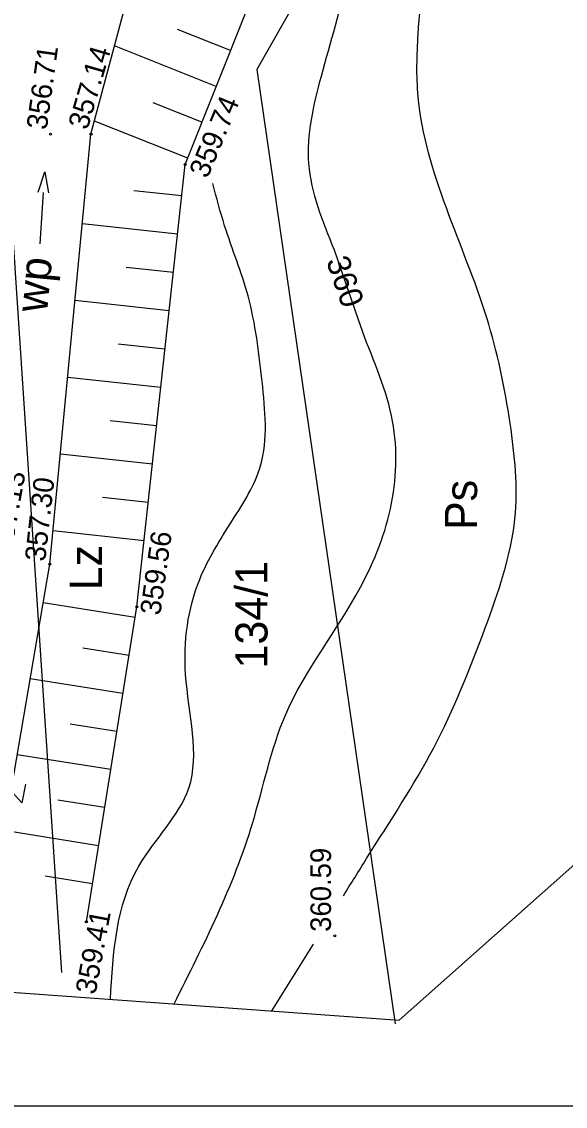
# Model space of a CAD drawing. Extents: x 4635329 to 4651863, y 5356628 to 5367582.
# Drawn here: x 4651202.03 to 4651223.16, y 5356627.73 to 5356669.94 of the extents above; entities that cross this region are included whole.
import ezdxf

# ---------------------------------------------------------------- set-up
doc = ezdxf.new("R2010")
doc.units = 0
for name, color, linetype in [('Level 1', 7, 'Continuous'), ('Level 12', 7, 'Continuous'), ('Level 13', 7, 'Continuous'), ('Level 4', 7, 'Continuous'), ('Level 44', 7, 'Continuous'), ('Level 45', 7, 'Continuous'), ('Level 46', 7, 'Continuous'), ('Level 47', 7, 'Continuous'), ('Level 48', 7, 'Continuous'), ('Level 5', 7, 'Continuous'), ('Level 50', 7, 'Continuous'), ('Level 51', 7, 'Continuous'), ('Level 53', 7, 'Continuous')]:
    doc.layers.add(name, color=color, linetype=linetype)

msp = doc.modelspace()

# ---------------------------------------------------------------- linework, layer by layer
at = {"layer": 'Level 1'}
for p, q in [((4651216.704, 5356631.078), (4651228.549, 5356641.621)), ((4651180.231, 5356633.731), (4651216.704, 5356631.078))]:
    msp.add_line(p, q, dxfattribs=at)
at = {"layer": 'Level 13'}
msp.add_lwpolyline([(4651092.18, 5356627.729), (4651092.18, 5356813.355), (4651331.195, 5356813.355), (4651331.195, 5356627.729)], close=True, dxfattribs=at)
at = {"layer": 'Level 4'}
for p, q in [((4651219.808, 5356683.279), (4651211.17, 5356668.081)), ((4651203.591, 5356632.939), (4651200.98, 5356672.325)), ((4651211.17, 5356668.081), (4651216.545, 5356630.936))]:
    msp.add_line(p, q, dxfattribs=at)
at = {"layer": 'Level 44'}
for centre in [(4651203.155, 5356665.557), (4651204.725, 5356665.557), (4651208.385, 5356664.377), (4651203.125, 5356648.827), (4651206.505, 5356647.167), (4651204.545, 5356634.907), (4651214.205, 5356634.367)]:
    msp.add_circle(centre, 0.04, dxfattribs=at)
at = {"layer": 'Level 46'}
for p, q in [((4651214.997, 5356658.707), (4651214.19, 5356661.051)), ((4651211.76, 5356631.438), (4651213.372, 5356634.04))]:
    msp.add_line(p, q, dxfattribs=at)
for points in [[(4651214.541, 5356635.926), (4651215.44, 5356637.377), (4651218.048, 5356641.682), (4651220.05, 5356646.351), (4651221.202, 5356650.595), (4651221.02, 5356654.294), (4651220.11, 5356658.417), (4651217.442, 5356667.027), (4651217.442, 5356669.452), (4651217.684, 5356673.818), (4651217.017, 5356677.759), (4651216.168, 5356680.79), (4651216.131, 5356681.56)], [(4651214.19, 5356661.051), (4651213.196, 5356664.419), (4651213.681, 5356667.815), (4651214.712, 5356671.756), (4651215.137, 5356675.94), (4651215.076, 5356678.426), (4651215.015, 5356680.305)], [(4651205.478, 5356631.895), (4651206.585, 5356637.074), (4651208.526, 5356640.106), (4651208.404, 5356644.532), (4651208.95, 5356648.23), (4651210.224, 5356650.534), (4651211.316, 5356652.657), (4651211.376, 5356655.931), (4651210.831, 5356659.266), (4651209.921, 5356661.994), (4651209.461, 5356663.637)], [(4651207.952, 5356631.715), (4651211.012, 5356638.772), (4651212.286, 5356642.955), (4651215.197, 5356647.927), (4651216.41, 5356651.201), (4651216.41, 5356654.597), (4651215.197, 5356658.114), (4651214.997, 5356658.707)]]:
    msp.add_spline(points, degree=3, dxfattribs=at)
at = {"layer": 'Level 48'}
for p, q in [((4651210.15, 5356668.811), (4651208.087, 5356669.632)), ((4651209.595, 5356667.417), (4651205.636, 5356668.993)), ((4651209.04, 5356666.023), (4651207.145, 5356666.778)), ((4651208.486, 5356664.63), (4651204.862, 5356666.072)), ((4651208.252, 5356663.156), (4651206.393, 5356663.359)), ((4651208.089, 5356661.665), (4651204.392, 5356662.069)), ((4651207.926, 5356660.174), (4651206.087, 5356660.375)), ((4651207.763, 5356658.683), (4651204.106, 5356659.082)), ((4651207.6, 5356657.192), (4651205.782, 5356657.39)), ((4651207.437, 5356655.701), (4651203.82, 5356656.096)), ((4651207.274, 5356654.209), (4651205.476, 5356654.406)), ((4651207.111, 5356652.718), (4651203.534, 5356653.109)), ((4651206.949, 5356651.227), (4651205.17, 5356651.421)), ((4651206.786, 5356649.736), (4651203.249, 5356650.122)), ((4651206.439, 5356646.757), (4651202.869, 5356647.327)), ((4651206.203, 5356645.275), (4651204.409, 5356645.562)), ((4651205.966, 5356643.794), (4651202.363, 5356644.37)), ((4651205.729, 5356642.313), (4651203.919, 5356642.602)), ((4651205.492, 5356640.832), (4651201.857, 5356641.413)), ((4651205.255, 5356639.351), (4651203.43, 5356639.642)), ((4651205.019, 5356637.869), (4651201.351, 5356638.456)), ((4651204.782, 5356636.388), (4651202.94, 5356636.683))]:
    msp.add_line(p, q, dxfattribs=at)
msp.add_lwpolyline([(4651204.545, 5356634.907), (4651206.505, 5356647.167), (4651208.385, 5356664.377), (4651210.845, 5356670.557), (4651215.615, 5356682.427), (4651219.555, 5356685.747)], dxfattribs=at)
at = {"layer": 'Level 50'}
for p, q in [((4651204.725, 5356665.557), (4651206.595, 5356672.607)), ((4651203.125, 5356648.827), (4651204.725, 5356665.557)), ((4651202.677, 5356663.303), (4651202.927, 5356664.089)), ((4651202.927, 5356664.089), (4651203.077, 5356663.278)), ((4651202.753, 5356661.294), (4651202.877, 5356663.29)), ((4651200.775, 5356635.087), (4651203.125, 5356648.827))]:
    msp.add_line(p, q, dxfattribs=at)
at = {"layer": 'Level 53'}
for p, q in [((4651202.039, 5356639.533), (4651201.201, 5356640.46)), ((4651202.183, 5356640.269), (4651202.039, 5356639.533))]:
    msp.add_line(p, q, dxfattribs=at)

# ---------------------------------------------------------------- texts
at = {"layer": 'Level 12'}
for s, p in [('Ps', (4651219.734, 5356650.156)), ('Lz', (4651205.147, 5356647.809))]:
    msp.add_text(s, height=1.25, rotation=90, dxfattribs=at).set_placement(p)
at = {"layer": 'Level 45'}
for s, rotation, p in [('356.71', 82.1568, (4651203.003, 5356665.704)), ('357.14', 73.6861, (4651204.587, 5356665.695)), ('359.74', 67.3911, (4651209.251, 5356663.802)), ('357.13', 79.681, (4651201.601, 5356649.156)), ('357.30', 83.617, (4651202.944, 5356648.908)), ('359.56', 81.9748, (4651207.417, 5356646.81)), ('360.59', 90, (4651214.055, 5356634.517)), ('359.41', 79.4563, (4651204.899, 5356632.051))]:
    msp.add_text(s, height=0.8, rotation=rotation, dxfattribs=at).set_placement(p)
at = {"layer": 'Level 47'}
msp.add_text('360', height=0.9, rotation=289.1156, dxfattribs=at).set_placement((4651213.856, 5356660.632))
at = {"layer": 'Level 5'}
msp.add_text('134/1', height=1.25, rotation=90, dxfattribs=at).set_placement((4651211.586, 5356644.767))
at = {"layer": 'Level 51'}
msp.add_text('wp', height=1.25, rotation=84.537, dxfattribs=at).set_placement((4651203.015, 5356658.591))

doc.saveas('drawing.dxf')
